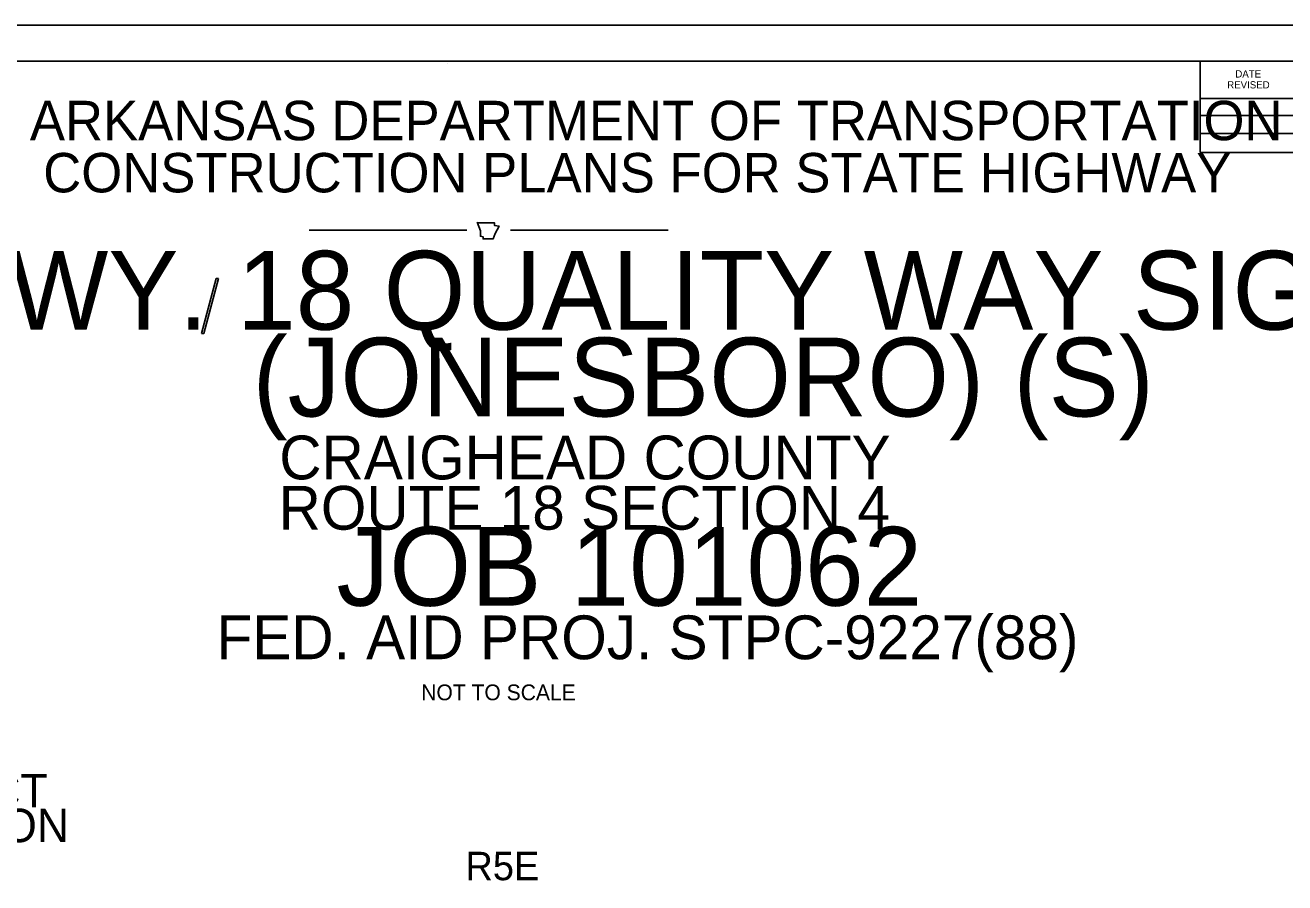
# Model space of a CAD drawing. Extents: x 646058 to 725608, y 1473014 to 1561048.
# Drawn here: x 671705 to 700985, y 1541123 to 1561048 of the extents above; entities that cross this region are included whole.
import ezdxf

# ---------------------------------------------------------------- set-up
doc = ezdxf.new("R2010")
doc.units = 0
for name, color, linetype in [('Default', 7, 'Continuous'), ('R_Border Notes', 7, 'Continuous'), ('R_Grid', 7, 'Continuous'), ('T_Vehicle Path Rt', 7, 'Continuous')]:
    doc.layers.add(name, color=color, linetype=linetype)

msp = doc.modelspace()

# ---------------------------------------------------------------- linework, layer by layer
at = {"layer": 'Default'}
for p, q in [((675805, 1553887), (676147, 1555164)), ((676199, 1555164), (675857, 1553887)), ((676147, 1555164), (676199, 1555164)), ((675857, 1553887), (675805, 1553887))]:
    msp.add_line(p, q, dxfattribs=at)
at = {"layer": 'R_Border Notes'}
for p, q in [((648725, 1560211), (716704, 1560211)), ((681517, 1560155), (681517, 1560155)), ((681517, 1560155), (681517, 1560155)), ((699018, 1558087), (699018, 1560211)), ((699018, 1559347), (707438, 1559347)), ((699018, 1558947), (707438, 1558947)), ((699018, 1558087), (699018, 1558530)), ((699018, 1558530), (707438, 1558530)), ((716704, 1558087), (699018, 1558087))]:
    msp.add_line(p, q, dxfattribs=at)
at = {"layer": 'R_Grid'}
for p, q in [((678308, 1556288), (681970, 1556288)), ((682988, 1556288), (686651, 1556288))]:
    msp.add_line(p, q, dxfattribs=at)
msp.add_lwpolyline([(682208, 1556474), (682287, 1556271), (682287, 1556146), (682350, 1556132), (682350, 1556084), (682581, 1556084), (682628, 1556209), (682722, 1556380), (682613, 1556395), (682613, 1556457), (682225, 1556457)], dxfattribs=at)
at = {"layer": 'T_Vehicle Path Rt'}
msp.add_line((646059, 1561048), (717726, 1561048), dxfattribs=at)
msp.add_lwpolyline([(646058, 1561048), (717726, 1561048), (717726, 1515181), (646058, 1515181)], close=True, dxfattribs=at)

# ---------------------------------------------------------------- texts
at = {"layer": 'Default'}
for s, height, p in [('HWY. 18 QUALITY WAY SIGNAL ', 1831.35, (669557, 1553974)), ('(JONESBORO) (S) ', 1831.35, (676990, 1551957)), ('CRAIGHEAD COUNTY', 1017.41, (677611, 1550496)), ('ROUTE 18 SECTION 4', 1017.41, (677595, 1549327)), ('JOB 101062', 1831.3, (678942, 1547560)), ('FED. AID PROJ. STPC-9227(88)', 1017.41, (676153, 1546317)), ('R5E', 660, (681938, 1541183))]:
    msp.add_text(s, height=height, dxfattribs=at).set_placement(p)
at = {"layer": 'R_Border Notes'}
for s, p in [('DATE', (699835, 1559833)), ('REVISED', (699646, 1559579))]:
    msp.add_text(s, height=168.1, rotation=360, dxfattribs=at).set_placement(p)
at = {"layer": 'R_Grid'}
for s, height, p in [('ARKANSAS DEPARTMENT OF TRANSPORTATION', 915.67, (671813, 1558376)), ('CONSTRUCTION PLANS FOR STATE HIGHWAY', 915.67, (672123, 1557164)), ('NOT TO SCALE', 366.27, (680910, 1545364)), ('PROJECT', 775.2, (667390, 1542874)), ('LOCATION', 775.2, (667426, 1542067))]:
    msp.add_text(s, height=height, dxfattribs=at).set_placement(p)

doc.saveas('drawing.dxf')
